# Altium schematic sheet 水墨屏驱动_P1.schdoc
size 297 x 209 mm; Symbol: Drawing-Symbol_A4; Company: 嘉立创EDA; Version: V1.0; Page Size: A4; @Project Name: 水墨屏demo1; @Page Count: 1; @Update Date: 2026-03-01; @Create Date: 2026-03-01; @Schematic Name: Schematic1; @Page No: 1; @Page Name: P1; Device: Drawing-Symbol_A4; @Board Name: Board1; @Create Time: 12:03:36; @Update Time: 12:03:36; @Assembly Variant: Basic; Border: 1; Title Block Position: 3; Size: A4; Width: 1170; Height: 825; Region Start: 1; X Region Count: 6; Y Region Count: 4; Blade Width: 10
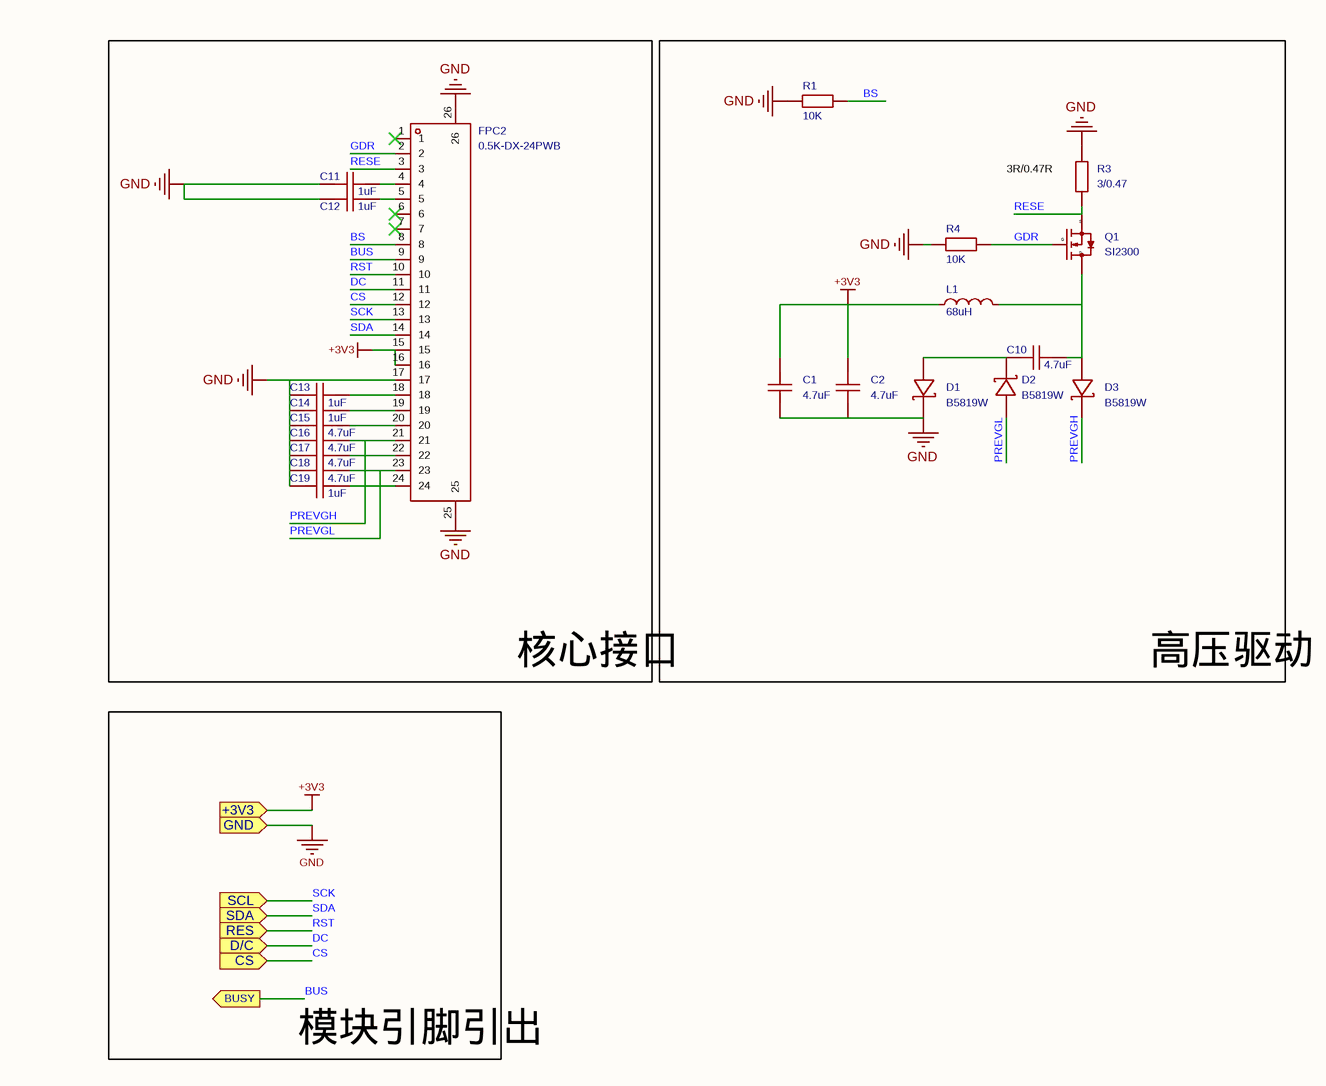
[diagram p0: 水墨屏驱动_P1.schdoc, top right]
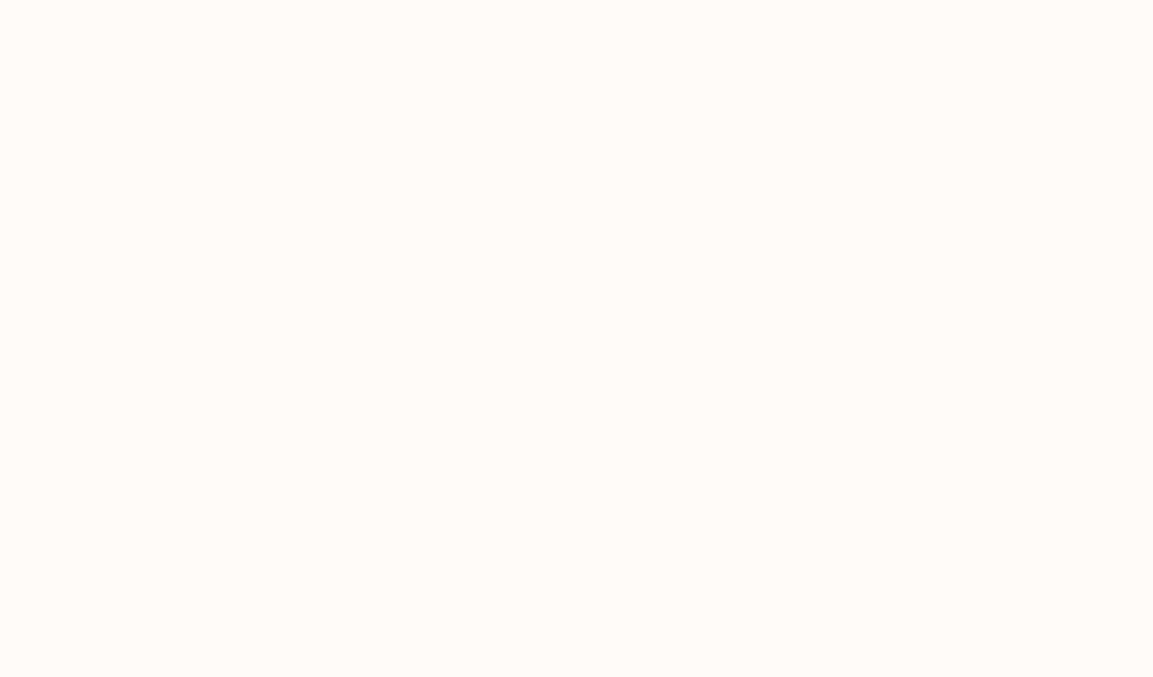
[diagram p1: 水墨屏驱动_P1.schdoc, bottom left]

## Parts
C1  4.7uF  [C0603]
C2  4.7uF  [C0603]
C10  4.7uF  [C0603]
C11  1uF  [C0603]
C12  1uF  [C0603]
C13  1uF  [C0603]
C14  1uF  [C0603]
C15  4.7uF  [C0603]
C16  4.7uF  [C0603]
C17  4.7uF  [C0603]
C18  4.7uF  [C0603]
C19  1uF  [C0603]
D1  B5819W  [SOD-123_L2.8-W1.8-LS3.7-RD]
D2  B5819W  [SOD-123_L2.8-W1.8-LS3.7-RD]
D3  B5819W  [SOD-123_L2.8-W1.8-LS3.7-RD]
FPC2  0.5K-DX-24PWB  [FPC-SMD_24P-P0.50_HDGC_0.5K-DX-24PWBG]
L1  68uH  [IND-SMD_L11.5-W10.5_SRG1040]
Q1  SI2300  [SOT-23-3_L2.9-W1.3-P1.90-LS2.4-BR]
R1  10K  [R0603]
R3  3/0.47  [R0603]
R4  10K  [R0603]

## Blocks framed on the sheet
核心接口: C11-C19 FPC2
高压驱动: C1 C2 C10 D1-D3 L1 Q1 R1 R3 R4

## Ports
+3V3 (in), BUSY (out), CS (in), D/C (in), GND (in), RES (in), SCL (in), SDA (in)

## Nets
+3V3: C1.2 C2.2 FPC2.15 FPC2.16 L1.1 ; port +3V3
GND: C1.1 C2.1 C11.1 C12.1 C13.1 C14.1 C15.1 C16.1 C17.1 C18.1 C19.1 D1.1(K) FPC2.17 FPC2.25 FPC2.26 R1.1 R3.2 R4.1 ; port GND
BS: FPC2.8 R1.2
BUS: FPC2.9 ; port BUSY
CS: FPC2.12 ; port CS
DC: FPC2.11 ; port D/C
GDR: FPC2.2 Q1.1(G) R4.2
PREVGH: C16.2 D3.1(K) FPC2.21
PREVGL: C18.2 D2.2(A) FPC2.23
RESE: FPC2.3 Q1.2(S) R3.1
RST: FPC2.10 ; port RES
SCK: FPC2.13 ; port SCL
SDA: FPC2.14 ; port SDA
NetC10_1: C10.1 D1.2(A) D2.1(K)
NetC10_2: C10.2 D3.2(A) L1.2 Q1.3(D)
NetC11_2: C11.2 FPC2.4
NetC12_2: C12.2 FPC2.5
NetC13_2: C13.2 FPC2.18
NetC14_2: C14.2 FPC2.19
NetC15_2: C15.2 FPC2.20
NetC17_2: C17.2 FPC2.22
NetC19_2: C19.2 FPC2.24

Not connected (* = marked no-connect by the designer): FPC2 1* 6* 7*

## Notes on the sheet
- (near R3) 3R/0.47R
- 模块引脚引出

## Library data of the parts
C1 C2 C10-C19 = CAP_0603: Symbol: CapAcitance; 3D Model: ac125912035d415993ca9572d50418b1; 3D Model Transform: 62.992,31.496,0,0,0,0,0,0,0; ConvertToPcb: yes; ModelName: C0603_L1.6-W0.8-H0.8
D1-D3 = B5819W_C64885: 直流反向耐压(Vr):40V;平均整流电流(Io):1A;正向压降(Vf):600mV@1A;; Manufacturer: MDD; 3D Model: 7884390a25fb4c08947731ebfba7e3f8; 3D Model Transform: 144.8816,62.992,0,0,0,0,0,0,0; Reverse Voltage (Vr): 40V; Average Rectified Current (Io): 1A; AddInBom: yes
FPC2 = 0.5K-DX-24PWB: FPC0.5间距2.0高掀盖式下接24P; Manufacturer: HDGC(华德共创); 3D Model: 268460ab2d1f4f59aa9b8c429d2ce240; 3D Model Transform: 685.4317,234.252,0,0,0,0,0,-49.527,0; AddInBom: yes
L1 = SRG1040-680-M: 电感值:68uH;精度:±20%;额定电流:2A;饱和电流(Isat):3A;类型:一体成型电感;; Manufacturer: JIERR(捷而瑞); 3D Model: 60d6566a84cc4ef9a23d25fbddc8792e0819f05c4eef4c71ace90d822a990e87; 3D Model Transform: 452.755,413.7787,0,0,0,0,-1.184,-2.756,0; Tolerance: ±20%; Current Rating: 2A; Current - Saturation(Isat): 3A; DC Resistance(DCR): 260mΩ; Type: 一体成型电感; AddInBom: yes
Q1 = SI2300_C181085: 类型:N沟道;漏源电压(Vdss):20V;连续漏极电流(Id):5A;功率(Pd):-;导通电阻(RDS(on)@Vgs,Id):60mΩ@2.5V,4A;阈值电压(Vgs(th)@Id):1.5V@250uA;; Manufacturer: Hottech(合科泰); 3D Model: c62791f0466c4ae2a892c056b845b0ca; 3D Model Transform: 98.425,114.173,0,180,0,0,0.0005,-0.0005,0; Type: N沟道; Drain Source Voltage (Vdss): 20V; Continuous Drain Current (Id): 5A; AddInBom: yes; ModelName: SOT-23-3P_L2.9-W1.3-H1.0-LS2.4-P0.95
R1 R3 R4 = Res_0603: Symbol: 电阻; 3D Model: fc143cca1e79419f9cd78b61e9279f08; 3D Model Transform: 31.8897,63.7794,0,90,0,0,0,0,0; ConvertToPcb: yes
